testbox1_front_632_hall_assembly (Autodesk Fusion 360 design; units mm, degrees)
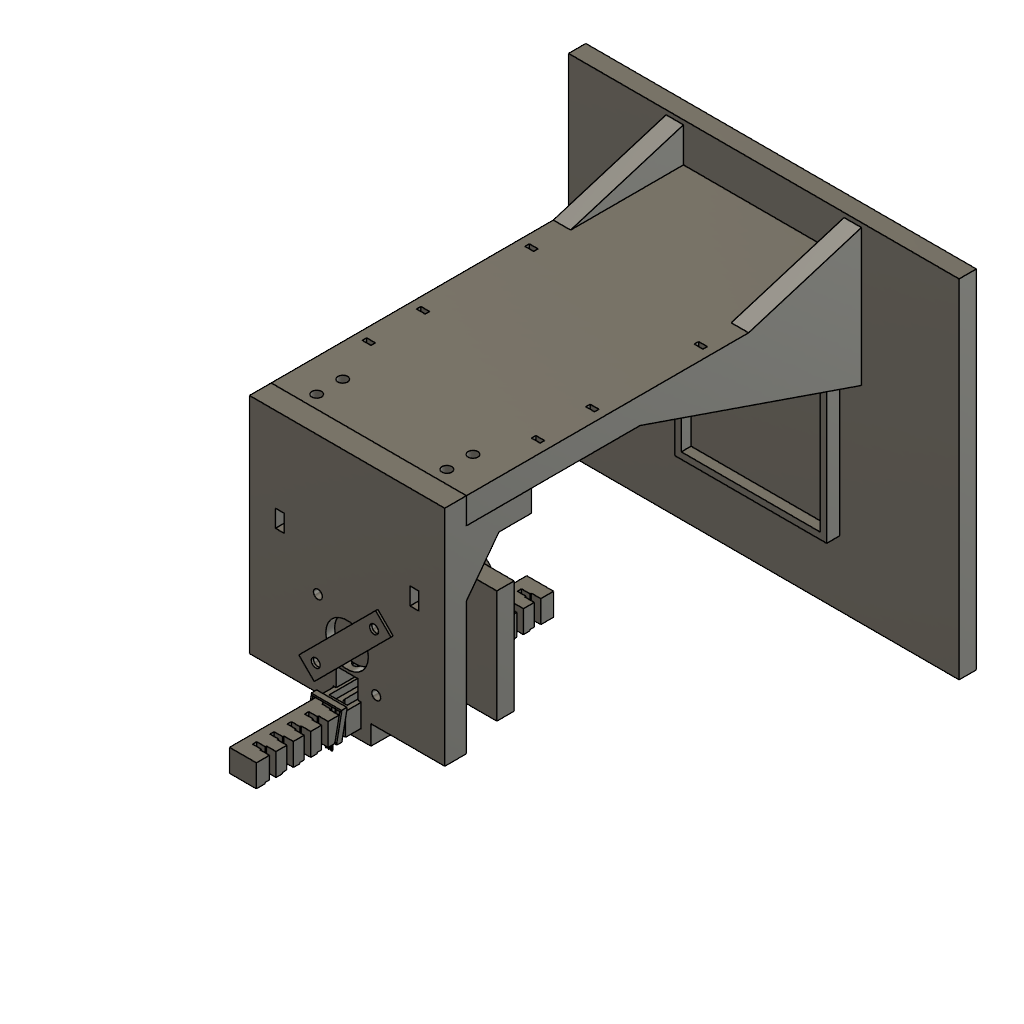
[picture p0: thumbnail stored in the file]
part number: 2026-11-14-21-39-58-941
part number: 2026-11-14-21-40-03-703
part number: 2026-11-14-21-40-03-710
part number: 2026-11-14-21-40-03-716
part number: 2026-11-14-21-40-03-721
part number: 2026-11-14-21-40-03-725
part number: 2026-11-14-21-40-03-735
part number: 2026-11-14-21-40-03-739
part number: 2026-11-14-21-40-03-743
part number: 2026-11-14-21-40-03-748
part number: 2026-11-14-21-40-03-752
part number: 2026-11-14-21-40-03-756
part number: 2026-11-14-21-40-03-761
part number: 2026-11-14-21-40-03-765
part number: 2026-11-14-21-40-03-769
part number: 2026-11-14-21-40-03-774
part number: 2026-11-14-21-40-03-780
part number: 2026-11-14-21-40-03-785
part number: 2026-11-14-21-40-03-790
part number: 2026-11-14-21-40-03-796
